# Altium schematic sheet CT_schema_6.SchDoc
size 280 x 236 mm
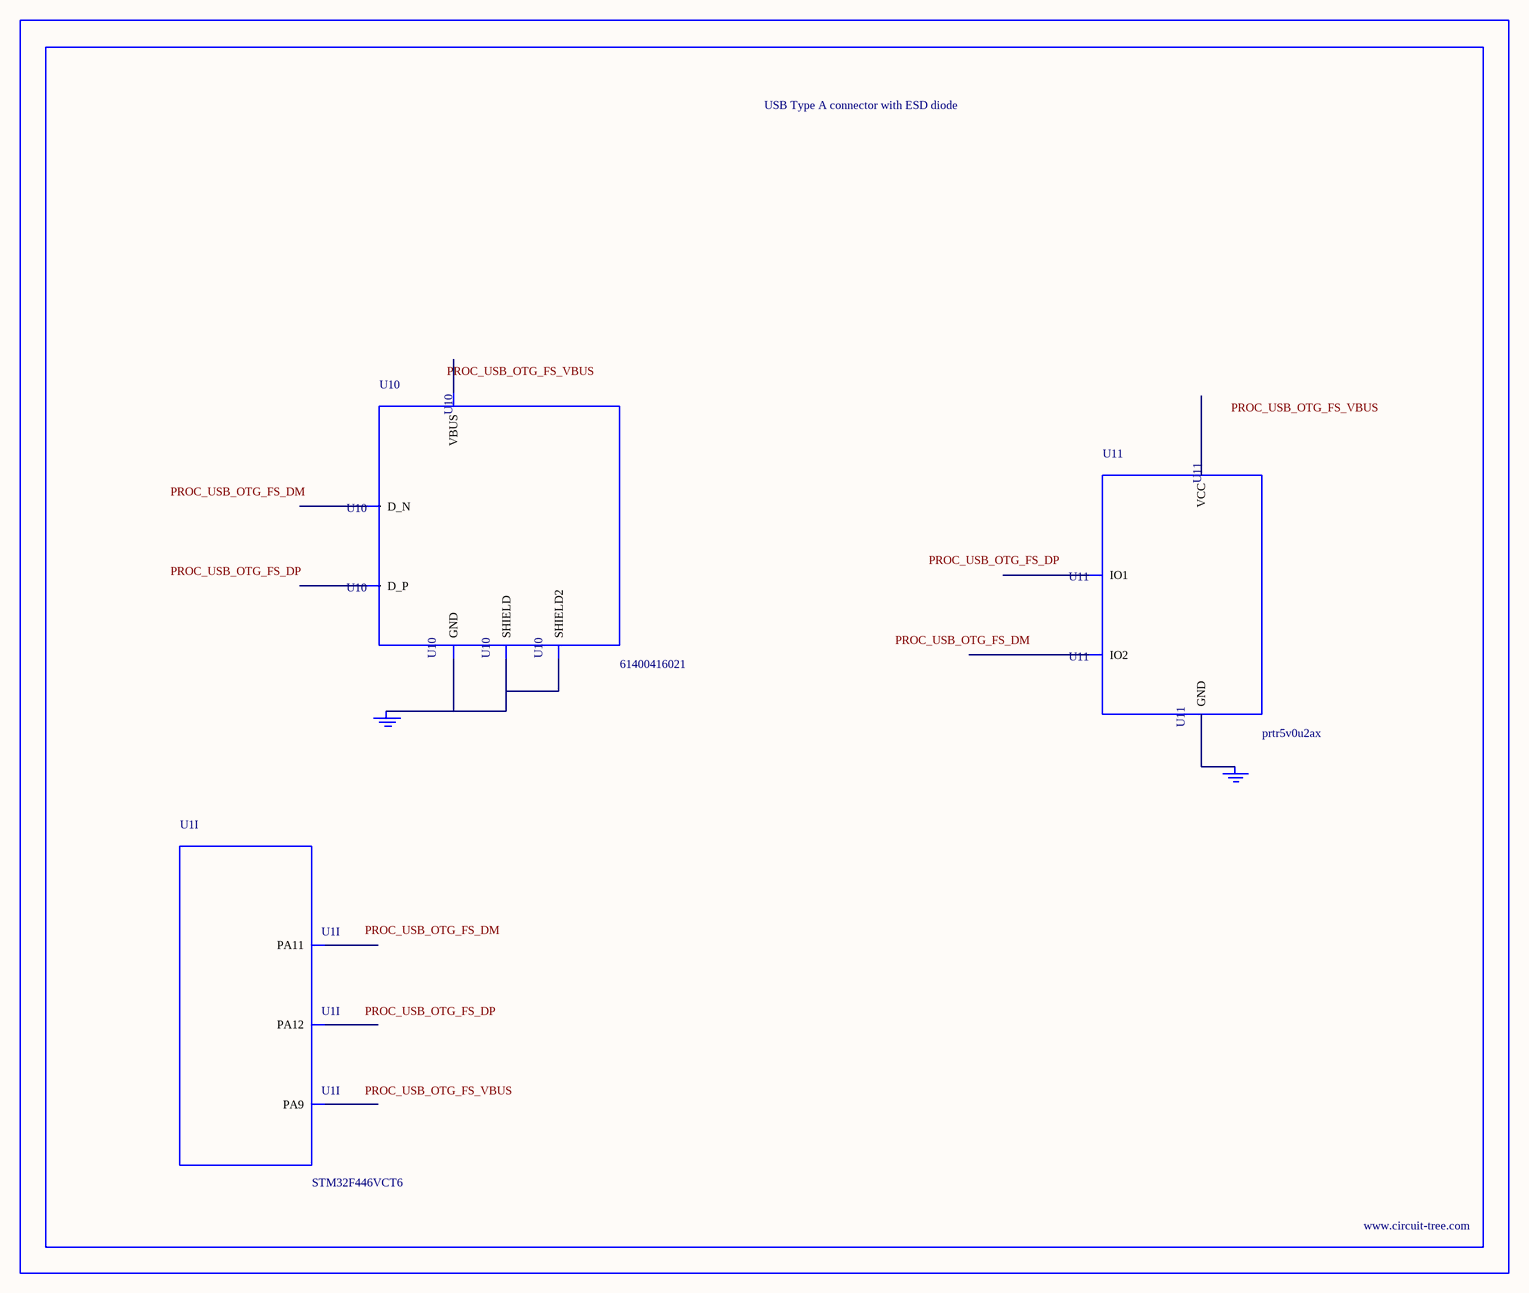
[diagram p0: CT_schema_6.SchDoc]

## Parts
BORDER5  (no value)
GND_INSTANCE_5_0  (no value)
GND_INSTANCE_5_1  (no value)
U1  STM32F446VCT6  [LQFP100]  (part I of 9)
U10  61400416021  [USB-A-H]
U11  prtr5v0u2ax  [SOT143B]

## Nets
NetGND_INSTANCE_5_0_0: GND_INSTANCE_5_0.0(GND) U10.4(GND) U10.5(SHIELD) U10.6(SHIELD2)
NetGND_INSTANCE_5_1_0: GND_INSTANCE_5_1.0(GND) U11.1(GND)

Not connected (* = marked no-connect by the designer): U1 68(PA9) 70(PA11) 71(PA12); U10 1(VBUS) 2(D_N) 3(D_P); U11 2(IO1) 3(IO2) 4(VCC)

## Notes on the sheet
- Labels drawn without touching a wire or pin: PROC_USB_OTG_FS_DM, PROC_USB_OTG_FS_DP, PROC_USB_OTG_FS_VBUS

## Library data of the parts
BORDER5 = BORDER_PAGE5
GND_INSTANCE_5_0 GND_INSTANCE_5_1 = GND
